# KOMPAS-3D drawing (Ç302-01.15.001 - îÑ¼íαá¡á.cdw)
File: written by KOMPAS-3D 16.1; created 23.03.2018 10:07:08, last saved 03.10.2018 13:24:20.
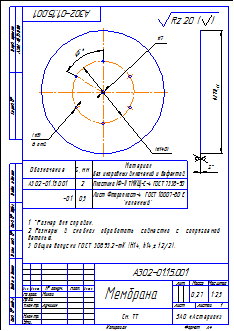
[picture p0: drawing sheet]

Sheet 1: A4, portrait

Title block, sheet 1: name: Мембрана; designation: А302-01.15.001; mass: 0,27; scale: 1:2,5; sheets: 1; organisation: ЗАО «Астерион»; sheet format: A4; stored path: \\192.168.87.28\Konstructor_doc\Мембранные насосы\Мембранный электропривод\А302-00.00.000 - ASTRA-302 (МЭ200)\Чертежи\А302-00.15.001 - Мембрана.cdw; designation, second copy: А302-01.15.001 - 01 -; drawn by: Милов; technical control: Лучихин

Views: Вид 1, Спереди, Проекционный вид 2
Referenced files in Z:\Мембранные насосы\Мембранный электропривод\А302-00.00.000 - ASTRA-302 (МЭ200)\3Д\: А302-00.15.001 - Мембрана.m3d
Referenced files in Z:\Мембранные насосы\Мембранный электропривод\А302-00.00.000 - ASTRA-302 (МЭ200)\3Д ПВХ\: А302-01.15.001 - Мембрана.m3d
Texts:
  См. ТТ
  S, мм
  без инородных включений и дефектов
  Лист Фторопласт-4  ГОСТ 10007-80 Е
  "каленный"
  Пластина  Ф-I  ТМКЩ-C-4 ГОСТ 7338-90
  *Размер для справок.
  Размеры в скобках обработать совместно с сопрягаемой
  деталью.
  Общие допуски ГОСТ 30893.2-mK (H14, h14,  t2/2).
  Rz 20
  Rz 20 ( )
Dimensions and other numbers on the sheet: 140; 5; 6 отв.; 7; 278; -01; 0,5; 2; 1:2,5; 1; 0,27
